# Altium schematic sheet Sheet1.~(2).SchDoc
size A4
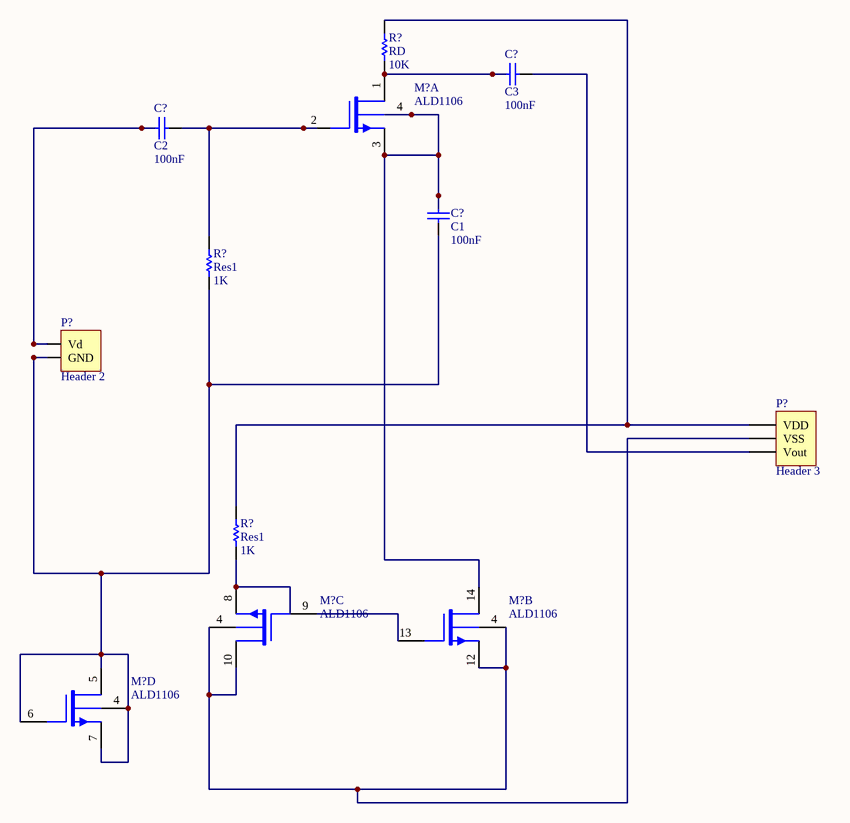
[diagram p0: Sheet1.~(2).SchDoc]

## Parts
(Parts that share a designator on the sheet are numbered #1, #2 ... from top to bottom, then left to right.)
C?#1  C3  value 100nF  [RAD-0.3]
C?#2  C2  value 100nF  [RAD-0.3]
C?#3  C1  value 100nF  [RAD-0.3]
M?#1  ALD1106  [DIP-14]  (part A of 4)
M?#2  ALD1106  [DIP-14]  (part C of 4)
M?#3  ALD1106  [DIP-14]  (part B of 4)
M?#4  ALD1106  [DIP-14]  (part D of 4)
P?#1  Header 2  [HDR1X2]
P?#2  Header 3  [HDR1X3]
R?#1  RD  value 10K  [AXIAL-0.3]
R?#2  Res1  value 1K  [AXIAL-0.3]
R?#3  Res1  value 1K  [AXIAL-0.3]

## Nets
NetC?#1_1: C?#1.1 M?#1.1(DN1) R?#1.1
NetC?#1_2: C?#1.2 P?#2.3(Vout)
NetC?#2_1: C?#2.1 P?#1.1(Vd)
NetC?#2_2: C?#2.2 M?#1.2(GN1) R?#2.2
NetC?#3_1: C?#3.1 M?#4.4(V-) M?#4.5(DN4) M?#4.6(GN4) M?#4.7(SN4) P?#1.2(GND) R?#2.1
NetC?#3_2: C?#3.2 M?#1.3(SN1) M?#1.4(V-) M?#3.14(DN2)
NetM?#2_4: M?#2.4(V-) M?#2.10(DN3) M?#3.4(V-) M?#3.12(SN2) P?#2.2(VSS)
NetM?#2_8: M?#2.8(SN3) R?#3.1
NetM?#2_9: M?#2.9(GN3) M?#3.13(GN2)
NetP?#2_1: P?#2.1(VDD) R?#1.2 R?#3.2

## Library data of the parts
C?#1-C?#3 = Cap: Capacitor
M?#1-M?#4 = ALD1106: Quad N-channel matched MOSFET array
P?#1 = Header 2: Header, 2-Pin
P?#2 = Header 3: Header, 3-Pin
R?#1-R?#3 = Res1: Resistor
